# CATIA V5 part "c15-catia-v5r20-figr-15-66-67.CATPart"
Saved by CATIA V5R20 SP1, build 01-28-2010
Part number: Part1
Bounding box of the stored display mesh (mm): x -68.209 to 30, y -98.209 to 60, z 0 to 98
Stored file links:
  D:\v5_r20\psrt_files_downloaded\c15\c15-catia-v5r20-figr-15-66-67.CATPart
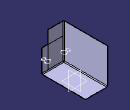
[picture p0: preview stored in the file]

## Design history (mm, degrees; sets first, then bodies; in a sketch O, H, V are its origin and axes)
SheetMetalParameters1: Thickness 1, BendRadius 2, KFactor 0.400515 {= log(min(100,max(20*SheetMetalParameters1.BendRadius,SheetMetalParameters1.Thickness)/SheetMetalParameters1.Thickness))/log(100)/2}, ReliefRadialLength 1, ReliefAxialLength 2, MinimumBendRadius 0
Body1 (main body)
  Sketch1 on xy-plane, origin (0, 0, 0), H (1, 0, 0), V (0, 1, 0)
    line L1 (-30, 60) -> (30, 60)
    line L2 (30, 60) -> (30, -60)
    line L3 (30, -60) -> (-30, -60)
    line L4 (-30, -60) -> (-30, 60)
    length L2 = 120
    length L1 = 60
    distance V L2 = 30
    distance H L1 = 60
    horizontal: L1 H, L3 H
    vertical: L2 V, L4 V
  Wall1: Thickness 1, Profile Sketch1
  d_NewWallOnEdge1: NewWallOnEdge_Edge edge [face of Wall1 | face of Wall1], NewWallOnEdge_Length 98, NewWallOnEdge_HeightLimitOffset 0, NewWallOnEdge_WidthOffset1 0, NewWallOnEdge_WidthOffset2 0, NewWallOnEdge_Angle 90, NewWallOnEdge_BendRadiusValue 2 {= SheetMetalParameters1.BendRadius}, NewWallOnEdge_BendTable SheetMetalParameters1, KFacteur 0.400515 {= log(min(100,max(20*d_NewWallOnEdge1.Radius,SheetMetalParameters1.Thickness)/SheetMetalParameters1.Thickness))/log(100)/2}
  d_NewWallOnEdge2: NewWallOnEdge_Edge edge [face of Wall1 | face of Wall1], NewWallOnEdge_Length 63, NewWallOnEdge_HeightLimitOffset 0, NewWallOnEdge_WidthOffset1 0, NewWallOnEdge_WidthOffset2 0, NewWallOnEdge_Angle 90, NewWallOnEdge_BendRadiusValue 2 {= SheetMetalParameters1.BendRadius}, NewWallOnEdge_BendTable SheetMetalParameters1, KFacteur 0.400515 {= log(min(100,max(20*d_NewWallOnEdge2.Radius,SheetMetalParameters1.Thickness)/SheetMetalParameters1.Thickness))/log(100)/2}
  d_NewWallOnEdge3: NewWallOnEdge_Edge edge [face of d_NewWallOnEdge1 | face of d_NewWallOnEdge1], NewWallOnEdge_Length 44, NewWallOnEdge_HeightLimitOffset 0, NewWallOnEdge_WidthOffset1 0, NewWallOnEdge_WidthOffset2 0, NewWallOnEdge_Angle 90, NewWallOnEdge_BendRadiusValue 2 {= SheetMetalParameters1.BendRadius}, NewWallOnEdge_BendTable SheetMetalParameters1, KFacteur 0.400515 {= log(min(100,max(20*d_NewWallOnEdge3.Radius,SheetMetalParameters1.Thickness)/SheetMetalParameters1.Thickness))/log(100)/2}
  Sketch2 on face of d_NewWallOnEdge3, origin (0, -60, 0), H (-1, 0, 0), V (0, 0, 1)
    circle A1 centre (8.1625, 34.9685) radius 4.4696
    circle A2 centre (8.1625, 23.754) radius 6.7449
    tangency: A2 A1
  SHMMapping1: CATSHMMappingContext d_NewWallOnEdge3, CATSHMMappingObject Sketch2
